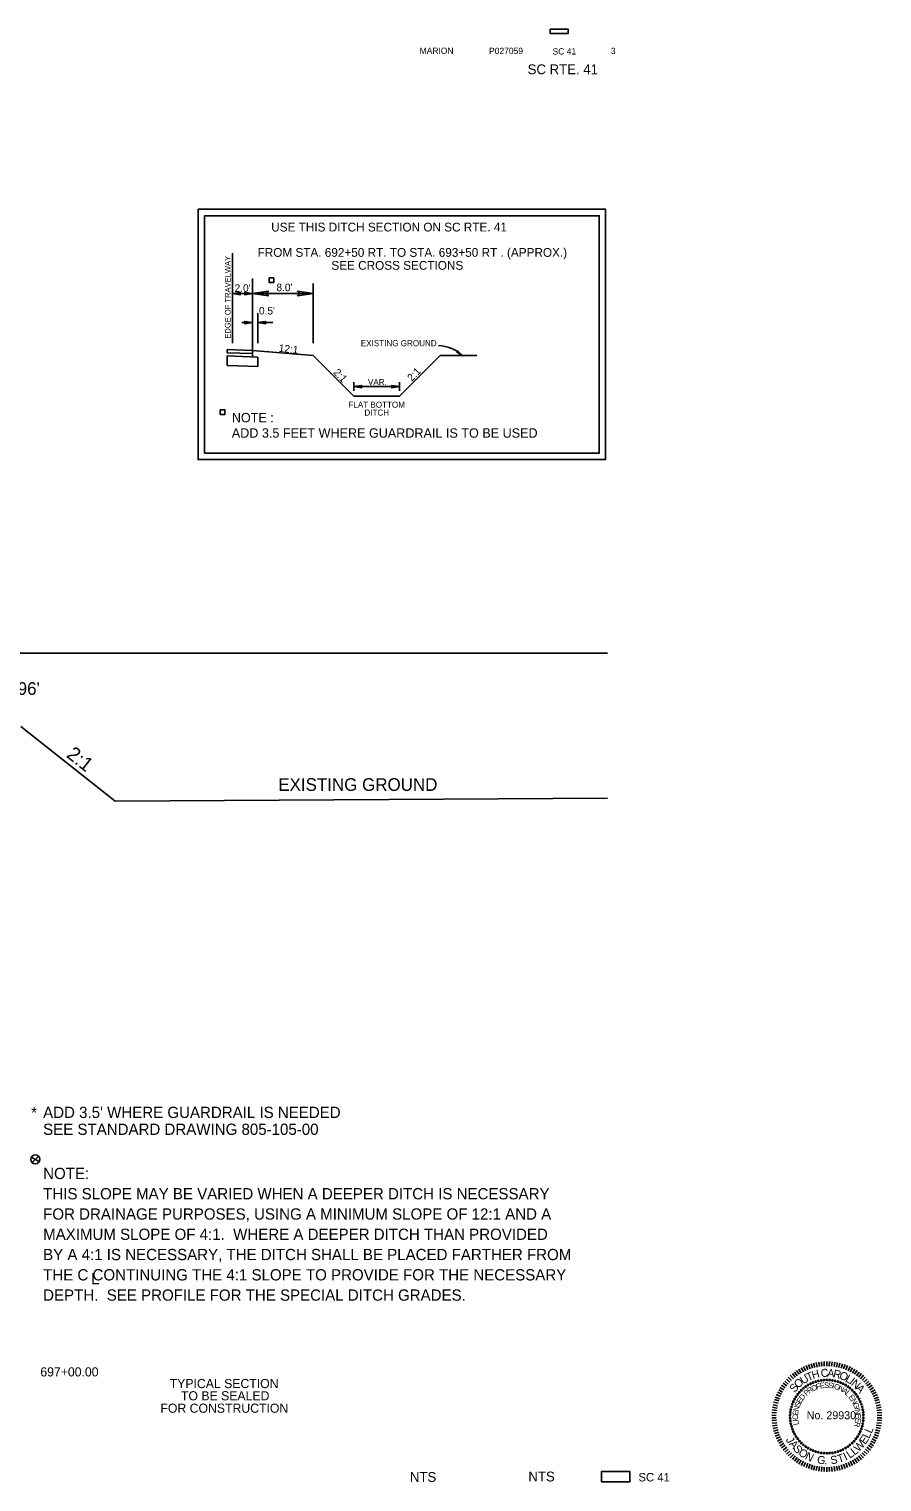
# Model space of a CAD drawing. Extents: x -8855 to -7045, y 42908 to 43943.
# Drawn here: x -7651 to -7045, y 42911 to 43943 of the extents above; entities that cross this region are included whole.
import ezdxf

# ---------------------------------------------------------------- set-up
doc = ezdxf.new("R2010")
doc.units = 0
for name, color, linetype in [('Default', 7, 'Continuous'), ('RD_EX_Misc', 7, 'Continuous'), ('RD_SHT_TX', 7, 'Continuous'), ('RD_TX_PEShield', 7, 'Continuous'), ('RD_TX_TypSect', 7, 'Continuous')]:
    doc.layers.add(name, color=color, linetype=linetype)

# ---------------------------------------------------------------- blocks, each defined once
blk = doc.blocks.new('STILLWELL')
at = {"layer": 'RD_TX_PEShield'}
for p, q in [((-19.7, 29.1), (-21.5, 31.8)), ((-18.2, 30), (-19.9, 32.8)), ((-16.7, 30.8), (-18.2, 33.7)), ((-15.1, 31.6), (-16.5, 34.6)), ((-13.6, 32.3), (-14.8, 35.3)), ((-11.9, 32.9), (-13, 36)), ((-10.3, 33.4), (-11.2, 36.6)), ((-8.6, 33.9), (-9.4, 37.1)), ((-6.9, 34.3), (-7.5, 37.5)), ((-5.2, 34.6), (-5.7, 37.8)), ((-3.5, 34.8), (-3.8, 38)), ((-1.8, 34.9), (-1.9, 38.2)), ((0, 34.9), (0, 38.2)), ((1.7, 34.9), (1.9, 38.2)), ((3.4, 34.8), (3.7, 38)), ((5.2, 34.6), (5.6, 37.8)), ((6.9, 34.3), (7.5, 37.5)), ((8.6, 33.9), (9.3, 37.1)), ((10.2, 33.4), (11.2, 36.6)), ((11.9, 32.9), (13, 36)), ((13.5, 32.3), (14.7, 35.3)), ((15.1, 31.6), (16.5, 34.6)), ((16.6, 30.8), (18.2, 33.7)), ((18.2, 30), (19.8, 32.8)), ((19.6, 29.1), (21.4, 31.8)), ((-29.5, 19.4), (-32.2, 21.3)), ((-28.5, 20.9), (-31.1, 22.8)), ((-27.4, 22.2), (-29.9, 24.3)), ((-26.3, 23.5), (-28.7, 25.7)), ((-25.1, 24.7), (-27.4, 27.1)), ((-23.8, 25.9), (-26, 28.4)), ((-22.5, 27), (-24.5, 29.6)), ((-21.1, 28.1), (-23, 30.7)), ((21.1, 28.1), (23, 30.7)), ((22.4, 27), (24.5, 29.6)), ((23.8, 25.9), (25.9, 28.4)), ((25, 24.7), (27.3, 27.1)), ((26.2, 23.5), (28.6, 25.7)), ((27.4, 22.2), (29.9, 24.3)), ((28.5, 20.9), (31.1, 22.8)), ((29.5, 19.4), (32.2, 21.3)), ((-34.1, 10.2), (-37.2, 11.2)), ((-33.6, 11.8), (-36.6, 12.9)), ((-32.9, 13.4), (-35.9, 14.7)), ((-32.2, 15), (-35.1, 16.4)), ((-31.4, 16.5), (-34.2, 18.1)), ((-30.5, 18), (-33.3, 19.7)), ((30.4, 18), (33.2, 19.7)), ((31.3, 16.5), (34.2, 18.1)), ((32.1, 15), (35.1, 16.4)), ((32.9, 13.4), (35.9, 14.7)), ((33.5, 11.8), (36.6, 12.9)), ((34.1, 10.2), (37.2, 11.2)), ((-35.9, -0.1), (-39.2, 0)), ((-35.8, 1.7), (-39.1, 1.9)), ((-35.6, 3.4), (-38.9, 3.8)), ((-35.4, 5.1), (-38.6, 5.7)), ((-35.1, 6.8), (-38.2, 7.5)), ((-34.6, 8.5), (-37.8, 9.4)), ((34.6, 8.5), (37.7, 9.4)), ((35, 6.8), (38.2, 7.5)), ((35.3, 5.1), (38.5, 5.7)), ((35.6, 3.4), (38.8, 3.8)), ((35.7, 1.7), (39, 1.9)), ((35.8, -0.1), (39.1, 0)), ((-35.9, -1.8), (-39.2, -1.9)), ((-35.8, -3.5), (-39.1, -3.8)), ((-35.6, -5.3), (-38.9, -5.6)), ((-35.4, -7), (-38.6, -7.5)), ((-35.1, -8.7), (-38.2, -9.4)), ((35, -8.7), (38.2, -9.4)), ((35.3, -7), (38.5, -7.5)), ((35.6, -5.3), (38.8, -5.6)), ((35.7, -3.5), (39, -3.8)), ((35.8, -1.8), (39.1, -1.9)), ((-34.6, -10.4), (-37.8, -11.2)), ((-34.1, -12), (-37.2, -13)), ((-33.6, -13.6), (-36.6, -14.8)), ((-32.9, -15.3), (-35.9, -16.6)), ((-32.2, -16.8), (-35.1, -18.3)), ((-31.4, -18.4), (-34.2, -19.9)), ((-30.5, -19.9), (-33.3, -21.6)), ((30.4, -19.9), (33.2, -21.6)), ((31.3, -18.4), (34.2, -19.9)), ((32.1, -16.8), (35.1, -18.3)), ((32.9, -15.3), (35.9, -16.6)), ((33.5, -13.6), (36.6, -14.8)), ((34.1, -12), (37.2, -13)), ((34.6, -10.4), (37.7, -11.2)), ((-29.5, -21.3), (-32.2, -23.2)), ((-28.5, -22.7), (-31.1, -24.7)), ((-27.4, -24.1), (-29.9, -26.2)), ((-26.3, -25.4), (-28.7, -27.6)), ((-25.1, -26.6), (-27.4, -28.9)), ((-23.8, -27.8), (-26, -30.2)), ((-22.5, -28.9), (-24.5, -31.4)), ((-21.1, -29.9), (-23, -32.6)), ((-19.7, -30.9), (-21.5, -33.7)), ((19.6, -30.9), (21.4, -33.7)), ((21.1, -29.9), (23, -32.6)), ((22.4, -28.9), (24.5, -31.4)), ((23.8, -27.8), (25.9, -30.2)), ((25, -26.6), (27.3, -28.9)), ((26.2, -25.4), (28.6, -27.6)), ((27.4, -24.1), (29.9, -26.2)), ((28.5, -22.7), (31.1, -24.7)), ((29.5, -21.3), (32.2, -23.2)), ((-18.2, -31.8), (-19.9, -34.7)), ((-16.7, -32.7), (-18.2, -35.6)), ((-15.1, -33.5), (-16.5, -36.4)), ((-13.6, -34.1), (-14.8, -37.2)), ((-11.9, -34.8), (-13, -37.8)), ((-10.3, -35.3), (-11.2, -38.4)), ((-8.6, -35.8), (-9.4, -38.9)), ((-6.9, -36.1), (-7.5, -39.3)), ((-5.2, -36.4), (-5.7, -39.7)), ((-3.5, -36.6), (-3.8, -39.9)), ((-1.8, -36.8), (-1.9, -40)), ((0, -36.8), (0, -40.1)), ((1.7, -36.8), (1.9, -40)), ((3.4, -36.6), (3.7, -39.9)), ((5.2, -36.4), (5.6, -39.7)), ((6.9, -36.1), (7.5, -39.3)), ((8.6, -35.8), (9.3, -38.9)), ((10.2, -35.3), (11.2, -38.4)), ((11.9, -34.8), (13, -37.8)), ((13.5, -34.1), (14.7, -37.2)), ((15.1, -33.5), (16.5, -36.4)), ((16.6, -32.7), (18.2, -35.6)), ((18.2, -31.8), (19.8, -34.7))]:
    blk.add_line(p, q, dxfattribs=at)
for centre in [(-15, 20.4), (-13.3, 21.5), (-11.6, 22.4), (-9.8, 23.2), (-7.9, 23.9), (-6, 24.4), (-4, 24.8), (-2, 25), (0, 25.1), (2, 25), (3.9, 24.8), (5.9, 24.4), (7.8, 23.9), (9.7, 23.2), (11.5, 22.4), (13.3, 21.5), (15, 20.4), (-22.9, 11.5), (-21.9, 13.2), (-20.7, 14.9), (-19.5, 16.4), (-18.1, 17.8), (-16.6, 19.2), (16.5, 19.2), (18, 17.8), (19.4, 16.4), (20.7, 14.9), (21.8, 13.2), (22.9, 11.5), (-26.1, 0.1), (-25.9, 2.1), (-25.6, 4), (-25.1, 6), (-24.5, 7.9), (-23.8, 9.7), (23.7, 9.7), (24.5, 7.9), (25.1, 6), (25.5, 4), (25.8, 2.1), (26, 0.1), (-26.1, -1.9), (-25.9, -3.9), (-25.6, -5.9), (-25.1, -7.8), (-24.5, -9.7), (24.5, -9.7), (25.1, -7.8), (25.5, -5.9), (25.8, -3.9), (26, -1.9), (-23.8, -11.6), (-22.9, -13.4), (-21.9, -15.1), (-20.7, -16.7), (-19.5, -18.3), (-18.1, -19.7), (-16.6, -21), (16.5, -21), (18, -19.7), (19.4, -18.3), (20.7, -16.7), (21.8, -15.1), (22.9, -13.4), (23.7, -11.6), (-15, -22.2), (-13.3, -23.3), (-11.6, -24.3), (-9.8, -25.1), (-7.9, -25.8), (-6, -26.3), (-4, -26.7), (-2, -26.9), (0, -27), (2, -26.9), (3.9, -26.7), (5.9, -26.3), (7.8, -25.8), (9.7, -25.1), (11.5, -24.3), (13.3, -23.3), (15, -22.2)]:
    blk.add_circle(centre, 0.49, dxfattribs=at)
for s, height, rotation, p in [('T', 5.68, 23.5044, (-13.2, 24.1)), ('H', 5.68, 16.1357, (-9.9, 25.6)), ('C', 5.68, 4.076, (-4.2, 27.1)), ('A', 5.68, 355.3651, (0.1, 27.4)), ('R', 5.68, 347.3188, (4.1, 27.1)), ('S', 5.68, 49.6435, (-22.9, 15.8)), ('O', 5.68, 41.5972, (-20.4, 18.8)), ('U', 5.68, 32.2152, (-16.9, 21.8)), ('O', 3.92, 24.9735, (-10, 16.9)), ('F', 3.92, 15.9995, (-7.1, 18.3)), ('E', 3.92, 8.9511, (-4.7, 19)), ('S', 3.92, 1.2546, (-1.9, 19.4)), ('S', 3.92, 353.558, (0.8, 19.5)), ('I', 3.92, 345.8615, (3.5, 19.2)), ('O', 3.92, 342.6583, (4.7, 19)), ('N', 3.92, 333.6842, (7.7, 18)), ('O', 5.68, 338.6079, (8.3, 26.2)), ('L', 5.68, 329.226, (12.6, 24.4)), ('I', 5.68, 322.5218, (15.5, 22.8)), ('N', 5.68, 319.1729, (16.8, 21.8)), ('A', 5.68, 310.4621, (20.1, 19)), ('E', 3.92, 60.2341, (-18.5, 7.9)), ('D', 3.92, 52.5376, (-17.1, 10.3)), ('P', 3.92, 41.0022, (-14.5, 13.5)), ('R', 3.92, 33.3057, (-12.5, 15.3)), ('A', 3.92, 325.3521, (10.4, 16.7)), ('L', 3.92, 317.6555, (12.6, 15.1)), ('E', 3.92, 308.0396, (15.1, 12.8)), ('N', 3.92, 300.343, (16.8, 10.6)), ('C', 3.92, 92.2915, (-20.4, -3.2)), ('E', 3.92, 83.9594, (-20.5, -0.2)), ('N', 3.92, 76.2628, (-20.2, 2.5)), ('S', 3.92, 67.9307, (-19.5, 5.4)), ('G', 3.92, 292.0109, (18.3, 8.1)), ('I', 3.92, 283.0368, (19.5, 5.1)), ('N', 3.92, 279.8336, (19.8, 4)), ('E', 3.92, 271.5014, (20.3, 1.1)), ('I', 3.92, 95.4947, (-20.2, -4.3)), ('L', 3.92, 101.9075, (-19.7, -6.6)), ('R', 3.92, 256.1083, (20.1, -4.4)), ('E', 3.92, 263.8049, (20.4, -1.7)), ('L', 5.68, 65.098, (31.6, -13.3)), ('J', 5.68, 299.033, (-29.4, -17.3)), ('A', 5.68, 310.5887, (-27.2, -20.6)), ('W', 5.68, 47.0518, (22.6, -26.4)), ('E', 5.68, 56.4327, (27.3, -21.1)), ('L', 5.68, 65.098, (30, -16.9)), ('S', 5.68, 310.5887, (-24.3, -24)), ('O', 5.68, 321.0072, (-20.8, -27.4)), ('N', 5.68, 333.4326, (-16, -30.8)), ('G', 5.68, 352.2045, (-7.2, -34.2)), ('S', 5.68, 8.0826, (2.9, -34.8)), ('T', 5.68, 18.9019, (8.5, -33.9)), ('I', 5.68, 25.3991, (13.3, -32.2)), ('L', 5.68, 34.0644, (16.2, -30.9)), ('L', 5.68, 37.6708, (19.6, -28.7)), ('.', 5.68, 0.8698, (-1.8, -34.9))]:
    blk.add_text(s, height=height, rotation=rotation, dxfattribs=at).set_placement(p)
blk.add_text('No. 29930', height=5.68, dxfattribs=at).set_placement((-14.3, -2.8))
blk = doc.blocks.new('AH')
at = {"layer": 'Default'}
blk.add_lwpolyline([(0, 0), (-10.39, 1.5), (-8.79, 0), (-10.39, -1.5)], close=True, dxfattribs=at)

msp = doc.modelspace()

# ---------------------------------------------------------------- linework, layer by layer
at = {"layer": 'Default'}
for p, q in [((-7849.3, 43499.3), (-7239.8, 43499.3)), ((-7656.4, 43447.2), (-7589.4, 43394.1)), ((-7589.4, 43394.1), (-7239.8, 43396.2))]:
    msp.add_line(p, q, dxfattribs=at)
for points in [[(-7530.6, 43814.7), (-7241.1, 43814.7), (-7241.1, 43636.9), (-7530.6, 43636.9)], [(-7526, 43810.1), (-7245.7, 43810.1), (-7245.7, 43641.5), (-7526, 43641.5)]]:
    msp.add_lwpolyline(points, close=True, dxfattribs=at)
at = {"layer": 'RD_EX_Misc'}
for p, q in [((-7506.1, 43719.6), (-7506.1, 43783.4)), ((-7491.8, 43714.4), (-7491.8, 43765.5)), ((-7506.1, 43754.8), (-7491.8, 43754.8)), ((-7491.8, 43754.8), (-7448.9, 43754.8)), ((-7448.9, 43719.6), (-7448.9, 43761.9)), ((-7491.8, 43734.2), (-7499.6, 43734.2)), ((-7488.2, 43719.6), (-7488.2, 43740.8)), ((-7477.5, 43734.2), (-7488.2, 43734.2)), ((-7509.9, 43715.1), (-7509.9, 43712.8)), ((-7491.8, 43714.4), (-7509.9, 43715.1)), ((-7509.9, 43712.8), (-7491.8, 43712.1)), ((-7509.9, 43712.8), (-7491.8, 43712.1)), ((-7491.8, 43714.4), (-7448.9, 43710.8)), ((-7491.8, 43712.1), (-7491.8, 43714.4)), ((-7491.8, 43714.4), (-7491.8, 43709.8)), ((-7509.9, 43710.5), (-7509.9, 43703.7)), ((-7488.2, 43709.7), (-7509.9, 43710.5)), ((-7509.9, 43703.7), (-7488.2, 43702.9)), ((-7508.2, 43703.7), (-7508.2, 43703.7)), ((-7502.7, 43710.2), (-7502.7, 43710.2)), ((-7502.7, 43710.2), (-7502.7, 43710.2)), ((-7488.2, 43702.9), (-7488.2, 43709.7)), ((-7419.9, 43681.8), (-7448.9, 43710.8)), ((-7387.6, 43681.8), (-7358.6, 43710.8)), ((-7358.6, 43710.8), (-7332.5, 43710.8)), ((-7358.6, 43710.8), (-7332.5, 43710.8)), ((-7419.9, 43685.6), (-7419.9, 43691.8)), ((-7387.6, 43685.6), (-7387.6, 43691.8)), ((-7419.9, 43688.7), (-7387.6, 43688.7)), ((-7419.9, 43681.8), (-7387.6, 43681.8))]:
    msp.add_line(p, q, dxfattribs=at)
msp.add_lwpolyline([(-7244, 42910.6), (-7224, 42910.6), (-7224, 42918), (-7244, 42918)], close=True, dxfattribs=at)
msp.add_arc((-7360.7, 43691.2), 26.6, 49.333, 87.9933, dxfattribs=at)
at = {"layer": 'RD_SHT_TX'}
msp.add_lwpolyline([(-7280.5, 43942.7), (-7267.8, 43942.7), (-7267.8, 43939.5), (-7280.5, 43939.5)], close=True, dxfattribs=at)
at = {"layer": 'RD_TX_TypSect'}
for p, q in [((-7649.1, 43141.2), (-7643.4, 43138.2)), ((-7648.4, 43137.5), (-7644, 43142))]:
    msp.add_line(p, q, dxfattribs=at)
for points in [[(-7480.1, 43765.9), (-7476.8, 43765.9), (-7476.8, 43762.7), (-7480.1, 43762.7)], [(-7514.8, 43672.1), (-7511.5, 43672.1), (-7511.5, 43668.9), (-7514.8, 43668.9)]]:
    msp.add_lwpolyline(points, close=True, dxfattribs=at)
msp.add_circle((-7646.2, 43139.7), 3.2, dxfattribs=at)

# ---------------------------------------------------------------- block references
at = {"layer": 'Default'}
msp.add_blockref('STILLWELL', (-7084, 42957.9), dxfattribs=at)
at = {"layer": 'RD_EX_Misc'}
for p, xscale, yscale, rotation in [((-7506.1, 43754.8), 0.5362500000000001, 0.5362500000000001, 180), ((-7491.8, 43754.8), 1.0725000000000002, -1.0725000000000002, 180), ((-7488.2, 43734.2), 0.5362500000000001, 0.5362500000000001, 180), ((-7343.4, 43711.3), 0.35750000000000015, 0.35750000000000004, -37.2536130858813), ((-7419.9, 43688.7), 0.5362500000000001, 0.5362500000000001, 180)]:
    msp.add_blockref('AH', p, dxfattribs=dict(at, xscale=xscale, yscale=yscale, rotation=rotation))
for p, xscale, yscale in [((-7491.8, 43754.8), 0.5362500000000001, 0.5362500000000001), ((-7448.9, 43754.8), 1.0725000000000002, 1.0725000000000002), ((-7491.8, 43734.2), 0.5362500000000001, 0.5362500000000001), ((-7387.6, 43688.7), 0.5362500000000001, 0.5362500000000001)]:
    msp.add_blockref('AH', p, dxfattribs=dict(at, xscale=xscale, yscale=yscale))

# ---------------------------------------------------------------- texts
for s, height, rotation, p in [('EDGE OF TRAVELWAY', 4.022, 90, (-7507.5, 43722.7)), ("0.5'", 5.36, 360, (-7487.3, 43739.9)), ('12:1', 5.36, 353.9912, (-7473.5, 43713.5)), ('2:1', 5.36, 46.752, (-7378.7, 43692)), ('2:1', 5.36, 313.248, (-7434.9, 43698.4)), ('2:1', 10, 321.5624, (-7624.7, 43426))]:
    msp.add_text(s, height=height, rotation=rotation, dxfattribs=at).set_placement(p)
for s, height, p in [("2.0'", 5.36, (-7504.6, 43756)), ("8.0'", 5.36, (-7474.9, 43756.5)), ('EXISTING GROUND', 4.29, (-7415, 43717.4)), ('VAR.', 4.29, (-7409.9, 43689.8)), ('FLAT BOTTOM', 4.29, (-7423.8, 43673.7)), ('DITCH', 4.29, (-7412.4, 43668.1)), ("0.96'", 9, (-7668.7, 43469.7)), ('EXISTING GROUND ', 9, (-7473.6, 43401.5)), ('NTS', 7, (-7380.1, 42910.6)), ('NTS', 7, (-7296, 42910.9)), ('SC 41', 6, (-7217.8, 42910.9))]:
    msp.add_text(s, height=height, dxfattribs=at).set_placement(p)
at = {"layer": 'RD_SHT_TX'}
for s, p in [('MARION', (-7373.2, 43925)), ('P027059', (-7323.9, 43924.9)), ('SC 41', (-7278.8, 43924.6)), ('3', (-7237.4, 43924.9))]:
    msp.add_text(s, height=4.5, rotation=0.0746, dxfattribs=at).set_placement(p)
for s, p in [('697+00.00', (-7642.6, 42985.5)), ('TYPICAL SECTION', (-7550.7, 42977.2)), ('TO BE SEALED ', (-7542.7, 42968.5)), ('FOR CONSTRUCTION', (-7557.3, 42959.7))]:
    msp.add_text(s, height=6.5, dxfattribs=at).set_placement(p)
at = {"layer": 'RD_TX_TypSect'}
for s, height, p in [('SC RTE. 41', 7, (-7296.5, 43910.6)), ('USE THIS DITCH SECTION ON SC RTE. 41 ', 6.24, (-7478.6, 43798.9)), ('FROM STA. 692+50 RT. TO STA. 693+50 RT . (APPROX.)     ', 6.24, (-7488.3, 43780.9)), ('SEE CROSS SECTIONS', 6.24, (-7435.9, 43771.7)), ('*', 8, (-7649.1, 43168.9)), ("ADD 3.5' WHERE GUARDRAIL IS NEEDED", 8, (-7640.6, 43169.1)), ('SEE STANDARD DRAWING 805-105-00', 8, (-7640.6, 43157.1)), ('NOTE:', 8, (-7640.6, 43125.7)), ('THIS SLOPE MAY BE VARIED WHEN A DEEPER DITCH IS NECESSARY', 8, (-7640.6, 43111.3)), ('FOR DRAINAGE PURPOSES, USING A MINIMUM SLOPE OF 12:1 AND A', 8, (-7640.6, 43096.9)), ('MAXIMUM SLOPE OF 4:1.  WHERE A DEEPER DITCH THAN PROVIDED', 8, (-7640.6, 43082.5)), ('BY A 4:1 IS NECESSARY, THE DITCH SHALL BE PLACED FARTHER FROM', 8, (-7640.6, 43068.1)), ('THE C CONTINUING THE 4:1 SLOPE TO PROVIDE FOR THE NECESSARY', 8, (-7640.6, 43053.7)), ('L', 8, (-7606.6, 43050.9)), ('DEPTH.  SEE PROFILE FOR THE SPECIAL DITCH GRADES.', 8, (-7640.6, 43039.3))]:
    msp.add_text(s, height=height, dxfattribs=at).set_placement(p)
for s, height, p in [('NOTE :', 6.69, (-7506.6, 43663.3)), ('ADD 3.5 FEET WHERE GUARDRAIL IS TO BE USED', 6.688, (-7506.6, 43652.4))]:
    msp.add_text(s, height=height, rotation=359.9949, dxfattribs=at).set_placement(p)

doc.saveas('drawing.dxf')
